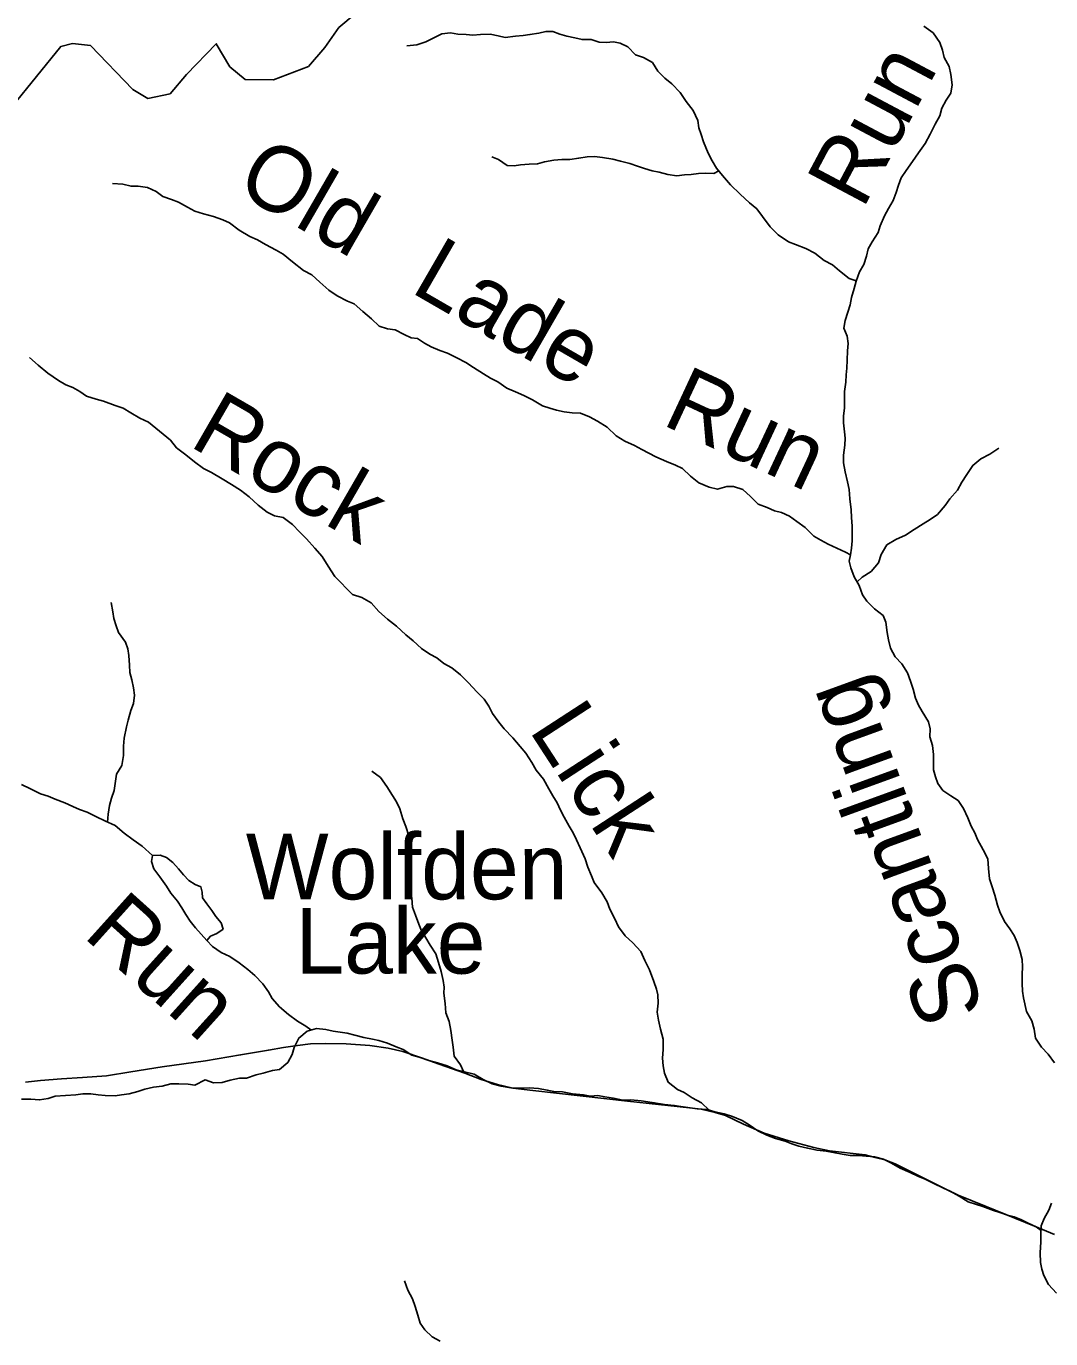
# Model space of a CAD drawing. Extents: x 0 to 34, y 0 to 22.
# Drawn here: x 4.582 to 6.061, y 17.257 to 19.152 of the extents above; entities that cross this region are included whole.
import ezdxf

# ---------------------------------------------------------------- set-up
doc = ezdxf.new("R2010")
doc.units = 0
for name, color, linetype in [('Default', 7, 'Continuous'), ('GM_X_Minor_Lake', 7, 'Continuous'), ('GM_X_Minor_Lake_Text', 7, 'Continuous'), ('GM_X_Minor_River', 7, 'Continuous'), ('GM_X_Minor_River_Text', 7, 'Continuous'), ('GM_X_State_Route', 7, 'Continuous')]:
    doc.layers.add(name, color=color, linetype=linetype)

msp = doc.modelspace()

# ---------------------------------------------------------------- linework, layer by layer
at = {"layer": 'Default'}
for points in [[(5.0571, 19.1699), (5.0333, 19.1501), (5.0133, 19.1215), (4.9895, 19.0941), (4.9393, 19.0746), (4.8984, 19.0751), (4.8762, 19.0936), (4.8566, 19.1269), (4.8136, 19.0823), (4.7898, 19.0545), (4.7579, 19.048), (4.7361, 19.0608), (4.6751, 19.1242), (4.6491, 19.1272), (4.632, 19.1229), (4.5616, 19.0361)], [(4.5616, 19.0361), (4.632, 19.1229), (4.6491, 19.1272), (4.6751, 19.1242), (4.7361, 19.0608), (4.7579, 19.048), (4.7898, 19.0545), (4.8136, 19.0823), (4.8566, 19.1269), (4.8762, 19.0936), (4.8984, 19.0751), (4.9393, 19.0746), (4.9895, 19.0941), (5.0133, 19.1215), (5.0333, 19.1501), (5.0571, 19.1699)]]:
    msp.add_lwpolyline(points, dxfattribs=at)
at = {"layer": 'GM_X_Minor_Lake'}
for points in [[(4.7645, 17.9547), (4.763, 17.9463), (4.7664, 17.9357), (4.775, 17.9239), (4.7848, 17.9105), (4.7908, 17.9006), (4.8005, 17.8888), (4.8069, 17.8792), (4.8126, 17.8697), (4.8189, 17.8601), (4.8265, 17.8506), (4.8427, 17.8322)], [(4.8427, 17.8322), (4.8484, 17.8383), (4.8571, 17.8424), (4.8663, 17.8487), (4.8637, 17.8579), (4.8558, 17.867), (4.8502, 17.8754), (4.8427, 17.885), (4.8367, 17.8938), (4.836, 17.9021), (4.8342, 17.9097), (4.8259, 17.9128), (4.8169, 17.9186), (4.8094, 17.927), (4.8019, 17.9358), (4.7936, 17.9449), (4.7846, 17.9522), (4.7755, 17.9553), (4.7645, 17.9547)]]:
    msp.add_lwpolyline(points, dxfattribs=at)
at = {"layer": 'GM_X_Minor_River'}
for points in [[(5.7804, 18.7845), (5.7705, 18.7881), (5.7565, 18.7992), (5.7463, 18.8076), (5.7342, 18.8138), (5.7207, 18.8245), (5.7078, 18.8314), (5.6927, 18.8372), (5.6825, 18.8411), (5.6677, 18.851), (5.6564, 18.8625), (5.6452, 18.8774), (5.6369, 18.8885), (5.6263, 18.8973), (5.6128, 18.9095), (5.5992, 18.9233), (5.5872, 18.9366), (5.5789, 18.9473), (5.5725, 18.958), (5.5669, 18.9691), (5.5598, 18.9854), (5.5568, 18.9957), (5.5535, 19.0056), (5.552, 19.0159), (5.5453, 19.0307), (5.5352, 19.0433), (5.5265, 19.0567), (5.5141, 19.0689), (5.5043, 19.0773), (5.4941, 19.0873), (5.4862, 19.0999), (5.4734, 19.1072), (5.4617, 19.111), (5.4508, 19.1225), (5.4398, 19.1275), (5.4299, 19.1298), (5.4193, 19.1288), (5.4095, 19.1292), (5.3977, 19.1331), (5.3848, 19.1328), (5.3742, 19.1355), (5.3625, 19.1379), (5.3527, 19.1406), (5.3425, 19.1448), (5.3322, 19.1445), (5.3223, 19.1423), (5.3094, 19.1401), (5.2996, 19.139), (5.2886, 19.1376), (5.2738, 19.1358), (5.2635, 19.1381), (5.2522, 19.1405), (5.2381, 19.1402), (5.2271, 19.1395), (5.2173, 19.1403), (5.2055, 19.1408), (5.1945, 19.1424), (5.182, 19.1413), (5.1687, 19.1346), (5.1592, 19.1297), (5.1463, 19.1252), (5.1315, 19.1238)], [(5.8338, 18.9005), (5.8384, 18.9122), (5.8415, 18.9225), (5.8454, 18.9335), (5.8527, 18.9441), (5.8618, 18.9569), (5.8706, 18.9694), (5.8802, 18.983), (5.8875, 18.9962), (5.8944, 19.011), (5.901, 19.0228), (5.9041, 19.0337), (5.9102, 19.0455), (5.9171, 19.0557), (5.9191, 19.0678), (5.9169, 19.0827), (5.9147, 19.0941), (5.9076, 19.107), (5.905, 19.1177), (5.9013, 19.1287), (5.8915, 19.1425), (5.8783, 19.1524)], [(5.5821, 18.9432), (5.5747, 18.9394), (5.5622, 18.9402), (5.5527, 18.9395), (5.5424, 18.9381), (5.5326, 18.9377), (5.5216, 18.9363), (5.5087, 18.9379), (5.4958, 18.9414), (5.486, 18.9434), (5.4746, 18.9469), (5.4648, 18.95), (5.4534, 18.9538), (5.4402, 18.9573), (5.4292, 18.9604), (5.414, 18.9628), (5.4027, 18.964), (5.3921, 18.9637), (5.3799, 18.9619), (5.367, 18.9597), (5.3556, 18.9598), (5.3439, 18.9587), (5.3306, 18.9565), (5.3203, 18.9535), (5.3082, 18.9532), (5.296, 18.9522), (5.2866, 18.9507), (5.2767, 18.9512), (5.2642, 18.9596), (5.2544, 18.9638)], [(5.7723, 18.3888), (5.7648, 18.3927), (5.7523, 18.3985), (5.7402, 18.4043), (5.7293, 18.41), (5.7191, 18.4158), (5.7066, 18.4284), (5.6949, 18.4372), (5.6844, 18.4449), (5.6726, 18.4499), (5.6624, 18.4526), (5.6518, 18.4572), (5.639, 18.4623), (5.6281, 18.473), (5.6167, 18.4833), (5.6031, 18.4876), (5.5936, 18.4876), (5.5803, 18.4839), (5.5682, 18.4866), (5.5535, 18.4928), (5.541, 18.5024), (5.5297, 18.5135), (5.5195, 18.5185), (5.5067, 18.5235), (5.4912, 18.5304), (5.481, 18.5358), (5.4711, 18.5412), (5.4602, 18.547), (5.4462, 18.5531), (5.4337, 18.5608), (5.4209, 18.5731), (5.407, 18.5819), (5.3956, 18.588), (5.3824, 18.5934), (5.3703, 18.5939), (5.3589, 18.5955), (5.3479, 18.5978), (5.3381, 18.6009), (5.3275, 18.604), (5.3131, 18.6129), (5.3006, 18.619), (5.2885, 18.6244), (5.2761, 18.6298), (5.2629, 18.6386), (5.2523, 18.644), (5.2425, 18.6502), (5.2281, 18.6594), (5.2168, 18.6667), (5.2039, 18.6736), (5.1903, 18.6801), (5.1794, 18.684), (5.1669, 18.6894), (5.1571, 18.6948), (5.1472, 18.7013), (5.1378, 18.7025), (5.1279, 18.7071), (5.1147, 18.7137), (5.1037, 18.7152), (5.0916, 18.7191), (5.0807, 18.7295), (5.0679, 18.7405), (5.0558, 18.7516), (5.046, 18.7551), (5.0309, 18.7628), (5.0188, 18.7713), (5.006, 18.7827), (4.9947, 18.7934), (4.9826, 18.7996), (4.9667, 18.8118), (4.9531, 18.823), (4.9429, 18.8287), (4.9278, 18.8368), (4.9161, 18.8437), (4.9048, 18.8487), (4.8897, 18.8575), (4.8757, 18.8683), (4.8659, 18.8725), (4.8523, 18.8775), (4.8383, 18.8814), (4.8258, 18.8853), (4.8152, 18.8907), (4.802, 18.898), (4.7921, 18.9022), (4.7793, 18.9065), (4.7695, 18.9134), (4.757, 18.9192), (4.7437, 18.9212), (4.7335, 18.9212), (4.7214, 18.9243), (4.7066, 18.9252)], [(6.0218, 17.7496), (6.0207, 17.759), (6.02, 17.77), (6.0201, 17.7829), (6.0206, 17.7943), (6.0202, 17.8046), (6.0169, 17.8175), (6.0128, 17.8293), (6.0087, 17.8392), (6.0023, 17.8491), (5.9948, 17.8594), (5.9877, 17.8735), (5.9844, 17.8834), (5.9807, 17.8975), (5.9766, 17.9097), (5.9729, 17.9211), (5.9714, 17.9363), (5.9704, 17.95), (5.964, 17.9633), (5.9554, 17.9782), (5.9517, 17.9877), (5.9464, 17.9973), (5.9416, 18.0094), (5.9352, 18.0228), (5.9277, 18.0342), (5.9172, 18.0411), (5.9058, 18.0488), (5.8983, 18.0587), (5.895, 18.0686), (5.892, 18.0785), (5.8921, 18.0914), (5.8922, 18.1009), (5.8907, 18.1138), (5.887, 18.126), (5.8871, 18.1378), (5.8849, 18.1477), (5.8755, 18.1626), (5.8706, 18.1721), (5.8662, 18.182), (5.8628, 18.1949), (5.8591, 18.2064), (5.8546, 18.2185), (5.8464, 18.2315), (5.8366, 18.2418), (5.8302, 18.254), (5.8273, 18.2662), (5.8254, 18.2768), (5.8233, 18.2917), (5.8192, 18.3016), (5.8071, 18.3111), (5.7958, 18.3219), (5.7898, 18.3314), (5.7849, 18.3447), (5.7774, 18.3573), (5.7726, 18.3702), (5.7704, 18.3797), (5.7724, 18.3892), (5.7739, 18.3987), (5.7748, 18.409), (5.7748, 18.4192), (5.7745, 18.4306), (5.7738, 18.4428), (5.7732, 18.4538), (5.7714, 18.4698), (5.7703, 18.4831), (5.7677, 18.4945), (5.7644, 18.5089), (5.7622, 18.5219), (5.7623, 18.5329), (5.7643, 18.5473), (5.7644, 18.5572), (5.7637, 18.5667), (5.7622, 18.5796), (5.7623, 18.5899), (5.7635, 18.6009), (5.7636, 18.6119), (5.7637, 18.6248), (5.7653, 18.6385), (5.7661, 18.6491), (5.7669, 18.6586), (5.7674, 18.67), (5.7679, 18.6833), (5.7691, 18.6943), (5.7676, 18.7045), (5.7624, 18.7163), (5.7647, 18.7273), (5.7682, 18.7395), (5.7717, 18.7501), (5.7737, 18.7607), (5.7776, 18.7736), (5.7803, 18.7842), (5.7853, 18.7975), (5.7915, 18.8081), (5.7953, 18.8202), (5.7977, 18.8308), (5.8034, 18.8407), (5.8122, 18.8543), (5.8153, 18.8641), (5.8215, 18.8785), (5.8273, 18.8888), (5.8338, 18.9005)], [(5.4943, 17.7536), (5.4921, 17.762), (5.4884, 17.773), (5.4821, 17.7898), (5.4753, 17.8031), (5.4693, 17.8161), (5.4581, 17.8287), (5.4471, 17.839), (5.4374, 17.852), (5.4321, 17.8634), (5.425, 17.8772), (5.4209, 17.8878), (5.413, 17.9012), (5.4021, 17.9157), (5.3984, 17.9256), (5.3928, 17.9381), (5.3891, 17.9503), (5.382, 17.9659), (5.3768, 17.9777), (5.3719, 17.9876), (5.3659, 17.9972), (5.3588, 18.0101), (5.3535, 18.0204), (5.3487, 18.0307), (5.3423, 18.041), (5.3367, 18.0513), (5.3288, 18.065), (5.3183, 18.078), (5.3119, 18.0891), (5.3033, 18.1024), (5.2954, 18.1123), (5.2848, 18.1246), (5.2724, 18.1379), (5.2645, 18.1475), (5.2555, 18.1601), (5.2499, 18.1704), (5.2431, 18.1807), (5.2329, 18.191), (5.2205, 18.204), (5.2092, 18.2155), (5.1968, 18.2258), (5.1851, 18.2323), (5.1749, 18.2404), (5.1651, 18.2457), (5.153, 18.2538), (5.1409, 18.2649), (5.13, 18.2733), (5.1168, 18.2859), (5.1036, 18.2963), (5.0911, 18.3074), (5.0802, 18.3196), (5.0666, 18.3273), (5.0534, 18.3319), (5.0278, 18.3579), (5.018, 18.3728), (5.0094, 18.3865), (4.9989, 18.3988), (4.9868, 18.4121), (4.9766, 18.4224), (4.9668, 18.4328), (4.9533, 18.4431), (4.9408, 18.4451), (4.9298, 18.4505), (4.917, 18.4608), (4.9042, 18.4727), (4.8917, 18.4822), (4.8785, 18.4903), (4.8649, 18.4987), (4.8494, 18.508), (4.8381, 18.5134), (4.8249, 18.5233), (4.8128, 18.5333), (4.7992, 18.5436), (4.7902, 18.5547), (4.7747, 18.5677), (4.7589, 18.5807), (4.746, 18.5865), (4.7332, 18.5942), (4.7219, 18.6007), (4.7105, 18.6046), (4.6939, 18.6108), (4.6833, 18.6135), (4.6693, 18.6181), (4.6595, 18.625), (4.6493, 18.6304), (4.6391, 18.6343), (4.6285, 18.6408), (4.6134, 18.6515), (4.5994, 18.663), (4.587, 18.6737)], [(5.7817, 18.3501), (5.7892, 18.3568), (5.8021, 18.3651), (5.8125, 18.3772), (5.8163, 18.3897), (5.8248, 18.4033), (5.8377, 18.4112), (5.8518, 18.4176), (5.8644, 18.4255), (5.8773, 18.4338), (5.8872, 18.4398), (5.8979, 18.4473), (5.909, 18.4601), (5.9159, 18.47), (5.9269, 18.4824), (5.9331, 18.4938), (5.9404, 18.5048), (5.9488, 18.518), (5.9602, 18.5278), (5.9732, 18.5342), (5.9865, 18.5432)], [(4.6997, 18.003), (4.7005, 18.0144), (4.7025, 18.0273), (4.7052, 18.0375), (4.7091, 18.0485), (4.7111, 18.0622), (4.7127, 18.0724), (4.7203, 18.0849), (4.7227, 18.0993), (4.7224, 18.1126), (4.7236, 18.1244), (4.7271, 18.1407), (4.7291, 18.1502), (4.733, 18.1642), (4.7368, 18.1744), (4.7384, 18.1866), (4.737, 18.1968), (4.7348, 18.2086), (4.7315, 18.2189), (4.7312, 18.2295), (4.7305, 18.2436), (4.7287, 18.2535), (4.7253, 18.263), (4.7155, 18.2767), (4.7122, 18.2863), (4.7085, 18.2969), (4.7074, 18.3068), (4.7048, 18.3201)], [(5.1853, 17.756), (5.1854, 17.7647), (5.1843, 17.7742), (5.181, 17.7876), (5.1776, 17.8005), (5.1735, 17.8127), (5.1653, 17.8253), (5.1589, 17.8359), (5.1529, 17.8462), (5.1488, 17.8558), (5.144, 17.8687), (5.1399, 17.8805), (5.1388, 17.8934), (5.1366, 17.906), (5.1352, 17.9189), (5.1345, 17.9303), (5.135, 17.9424), (5.1347, 17.9527), (5.1355, 17.9645), (5.1359, 17.974), (5.1345, 17.9835), (5.13, 17.9968), (5.1259, 18.0078), (5.1215, 18.0223), (5.1166, 18.0322), (5.111, 18.0417), (5.1027, 18.0547), (5.0937, 18.0673), (5.0813, 18.0765)], [(4.932, 17.7579), (4.9238, 17.7698), (4.9121, 17.7817), (4.9023, 17.7901), (4.8894, 17.7997), (4.8762, 17.8089), (4.8634, 17.815), (4.8513, 17.8235), (4.8427, 17.8322), (4.8265, 17.8506), (4.8189, 17.8601), (4.8126, 17.8697), (4.8069, 17.8792), (4.8005, 17.8888), (4.7908, 17.9006), (4.7848, 17.9105), (4.775, 17.9239), (4.7664, 17.9357), (4.763, 17.9463), (4.7645, 17.9547), (4.7495, 17.9685), (4.7363, 17.9777), (4.7235, 17.9872), (4.7106, 17.998), (4.6955, 18.0049), (4.6834, 18.0107), (4.6702, 18.0176), (4.6592, 18.0211), (4.6494, 18.0257), (4.6381, 18.0307), (4.6241, 18.0361), (4.6139, 18.0404), (4.6029, 18.0439), (4.5885, 18.0512), (4.5753, 18.0573)], [(4.9931, 17.703), (4.9859, 17.7087), (4.9738, 17.7159), (4.9609, 17.7251), (4.948, 17.7362), (4.9371, 17.7484), (4.932, 17.7579)], [(5.2134, 17.643), (5.209, 17.6527), (5.2, 17.6653), (5.1986, 17.6782), (5.1971, 17.6885), (5.1953, 17.7022), (5.1927, 17.7151), (5.1878, 17.7276), (5.1868, 17.7413), (5.1853, 17.756)], [(5.5683, 17.5872), (5.5573, 17.5976), (5.5436, 17.6052), (5.5319, 17.6125), (5.5224, 17.6171), (5.5092, 17.6275), (5.5039, 17.6404), (5.5017, 17.6511), (5.5007, 17.6624), (5.5019, 17.675), (5.502, 17.6898), (5.4979, 17.7042), (5.4949, 17.7172), (5.4931, 17.7289), (5.4947, 17.7418), (5.4943, 17.7536)], [(6.0666, 17.6554), (6.0576, 17.668), (6.0478, 17.6783), (6.0395, 17.6913), (6.0373, 17.7042), (6.0343, 17.7164), (6.0264, 17.7297), (6.0218, 17.7496)], [(6.0475, 17.4137), (6.0405, 17.419), (6.0287, 17.424), (6.0192, 17.429), (6.0086, 17.4332), (5.9991, 17.4356), (5.9881, 17.4394), (5.9786, 17.4425), (5.9635, 17.4483), (5.954, 17.451), (5.9422, 17.4549), (5.929, 17.4629), (5.9161, 17.4702), (5.9066, 17.4748), (5.8926, 17.4814), (5.8801, 17.4875), (5.8702, 17.4914), (5.8585, 17.4971), (5.8441, 17.5033), (5.8304, 17.511), (5.8198, 17.5167), (5.8069, 17.5198), (5.7948, 17.521), (5.7845, 17.5219), (5.772, 17.5219), (5.7602, 17.5239), (5.7499, 17.5255), (5.737, 17.5278), (5.7241, 17.5294), (5.7104, 17.5325), (5.6975, 17.5353), (5.6877, 17.5387), (5.6778, 17.5426), (5.6638, 17.5461), (5.6516, 17.5511), (5.6384, 17.5572), (5.6259, 17.566), (5.6157, 17.5722), (5.602, 17.5783), (5.5899, 17.5818), (5.5766, 17.5849), (5.5652, 17.588), (5.5508, 17.5893), (5.5375, 17.5912), (5.5272, 17.5924), (5.5177, 17.594), (5.5037, 17.5952), (5.4889, 17.598), (5.4794, 17.5992), (5.4699, 17.6007), (5.455, 17.6023), (5.4436, 17.6016), (5.43, 17.6044), (5.4174, 17.6063), (5.4072, 17.6083), (5.3965, 17.6076), (5.3867, 17.6092), (5.3707, 17.6108), (5.3563, 17.6135), (5.3437, 17.6144), (5.3343, 17.6163), (5.3217, 17.6183), (5.3084, 17.6195), (5.2947, 17.6188), (5.2818, 17.6196), (5.2681, 17.622), (5.2549, 17.6251), (5.242, 17.6313), (5.2287, 17.6393), (5.2029, 17.6455), (5.19, 17.6513), (5.176, 17.6556), (5.1635, 17.6587), (5.1494, 17.6637), (5.1388, 17.6668), (5.1263, 17.6748), (5.1164, 17.6787), (5.1036, 17.6841), (5.0914, 17.6879), (5.0819, 17.6899), (5.0694, 17.6919), (5.0565, 17.6954), (5.0455, 17.6985), (5.0356, 17.6996), (5.0254, 17.7012), (5.0147, 17.7036), (5.0011, 17.7052), (4.9877, 17.7014), (4.9759, 17.6913), (4.9689, 17.6776), (4.9662, 17.6678), (4.9597, 17.656), (4.9478, 17.6458), (4.9376, 17.6444), (4.9242, 17.6407), (4.914, 17.6381), (4.9002, 17.6332), (4.89, 17.6333), (4.8767, 17.6303), (4.8652, 17.6273), (4.8523, 17.6266)], [(4.8523, 17.6266), (4.8406, 17.6309), (4.8257, 17.6234), (4.8158, 17.6249), (4.8025, 17.6254), (4.7911, 17.6251), (4.7785, 17.6221), (4.766, 17.6203), (4.7534, 17.6173), (4.7431, 17.614), (4.7306, 17.611), (4.7199, 17.6095), (4.7104, 17.6081), (4.6963, 17.6085), (4.6861, 17.6094), (4.6754, 17.6106), (4.6637, 17.611), (4.6538, 17.6095), (4.6386, 17.6085), (4.6237, 17.6074), (4.6138, 17.6041), (4.6013, 17.6019), (4.5887, 17.6031), (4.5751, 17.6032)], [(6.0699, 17.3231), (6.0582, 17.3357), (6.0514, 17.3483), (6.0484, 17.3578), (6.0466, 17.3673), (6.0463, 17.3814), (6.0472, 17.3969), (6.0472, 17.4072), (6.0477, 17.4201), (6.0519, 17.4307), (6.0585, 17.4428), (6.0623, 17.4527)], [(5.1799, 17.2538), (5.1682, 17.2599), (5.1576, 17.2702), (5.1508, 17.2798), (5.1475, 17.2912), (5.1438, 17.3037), (5.1396, 17.3148), (5.1333, 17.3273), (5.1284, 17.3406)]]:
    msp.add_lwpolyline(points, dxfattribs=at)
at = {"layer": 'GM_X_State_Route'}
msp.add_lwpolyline([(4.5809, 17.6275), (4.6029, 17.6301), (4.6332, 17.6326), (4.6636, 17.6342), (4.6982, 17.6369), (4.7332, 17.6425), (4.7784, 17.6496), (4.8408, 17.6586), (4.8915, 17.667), (4.9318, 17.674), (4.9534, 17.6775), (4.9736, 17.6805), (4.9927, 17.6828), (5.0141, 17.6837), (5.0441, 17.6829), (5.0784, 17.6805), (5.1046, 17.6768), (5.1261, 17.6721), (5.153, 17.663), (5.1782, 17.6538), (5.2156, 17.6407), (5.2392, 17.6315), (5.2625, 17.6241), (5.2849, 17.6192), (5.3136, 17.6155), (5.4502, 17.6003), (5.5398, 17.5908), (5.5568, 17.5885), (5.577, 17.584), (5.5918, 17.5794), (5.6177, 17.5668), (5.6476, 17.554), (5.6831, 17.5428), (5.7192, 17.5332), (5.742, 17.5285), (5.7593, 17.5266), (5.7762, 17.5245), (5.7932, 17.5225), (5.8081, 17.5191), (5.822, 17.5153), (5.8368, 17.5098), (5.9108, 17.4728), (5.9276, 17.4644), (5.968, 17.4481), (6.0378, 17.4198), (6.0668, 17.4079)], dxfattribs=at)

# ---------------------------------------------------------------- texts
at = {"layer": 'GM_X_Minor_Lake_Text'}
for s, rotation, p in [('Wolfden', 0, (4.8992, 17.8916)), ('Lake', 0.0001, (4.9707, 17.7844))]:
    msp.add_text(s, height=0.09469, rotation=rotation, dxfattribs=at).set_placement(p)
at = {"layer": 'GM_X_Minor_River_Text'}
for s, rotation, p in [('Run', 62.0029, (5.7899, 18.8865)), ('Old', 329.9984, (4.8816, 18.9148)), ('Lade', 329.999, (5.1349, 18.7695)), ('Run', 334.9994, (5.498, 18.578)), ('Rock', 329.999, (4.8155, 18.5472)), ('Scantling', 110.0013, (5.9664, 17.7314)), ('Lick', 303.0001, (5.3068, 18.1365)), ('Run', 317.9995, (4.6626, 17.8384))]:
    msp.add_text(s, height=0.0947, rotation=rotation, dxfattribs=at).set_placement(p)

doc.saveas('drawing.dxf')
